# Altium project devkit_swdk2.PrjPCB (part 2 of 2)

## Sheet Application Interfaces.SchDoc: APPLICATION INTERFACES
size B; DocumentNumber: 5; SheetNumber: 5; SheetTotal: 6
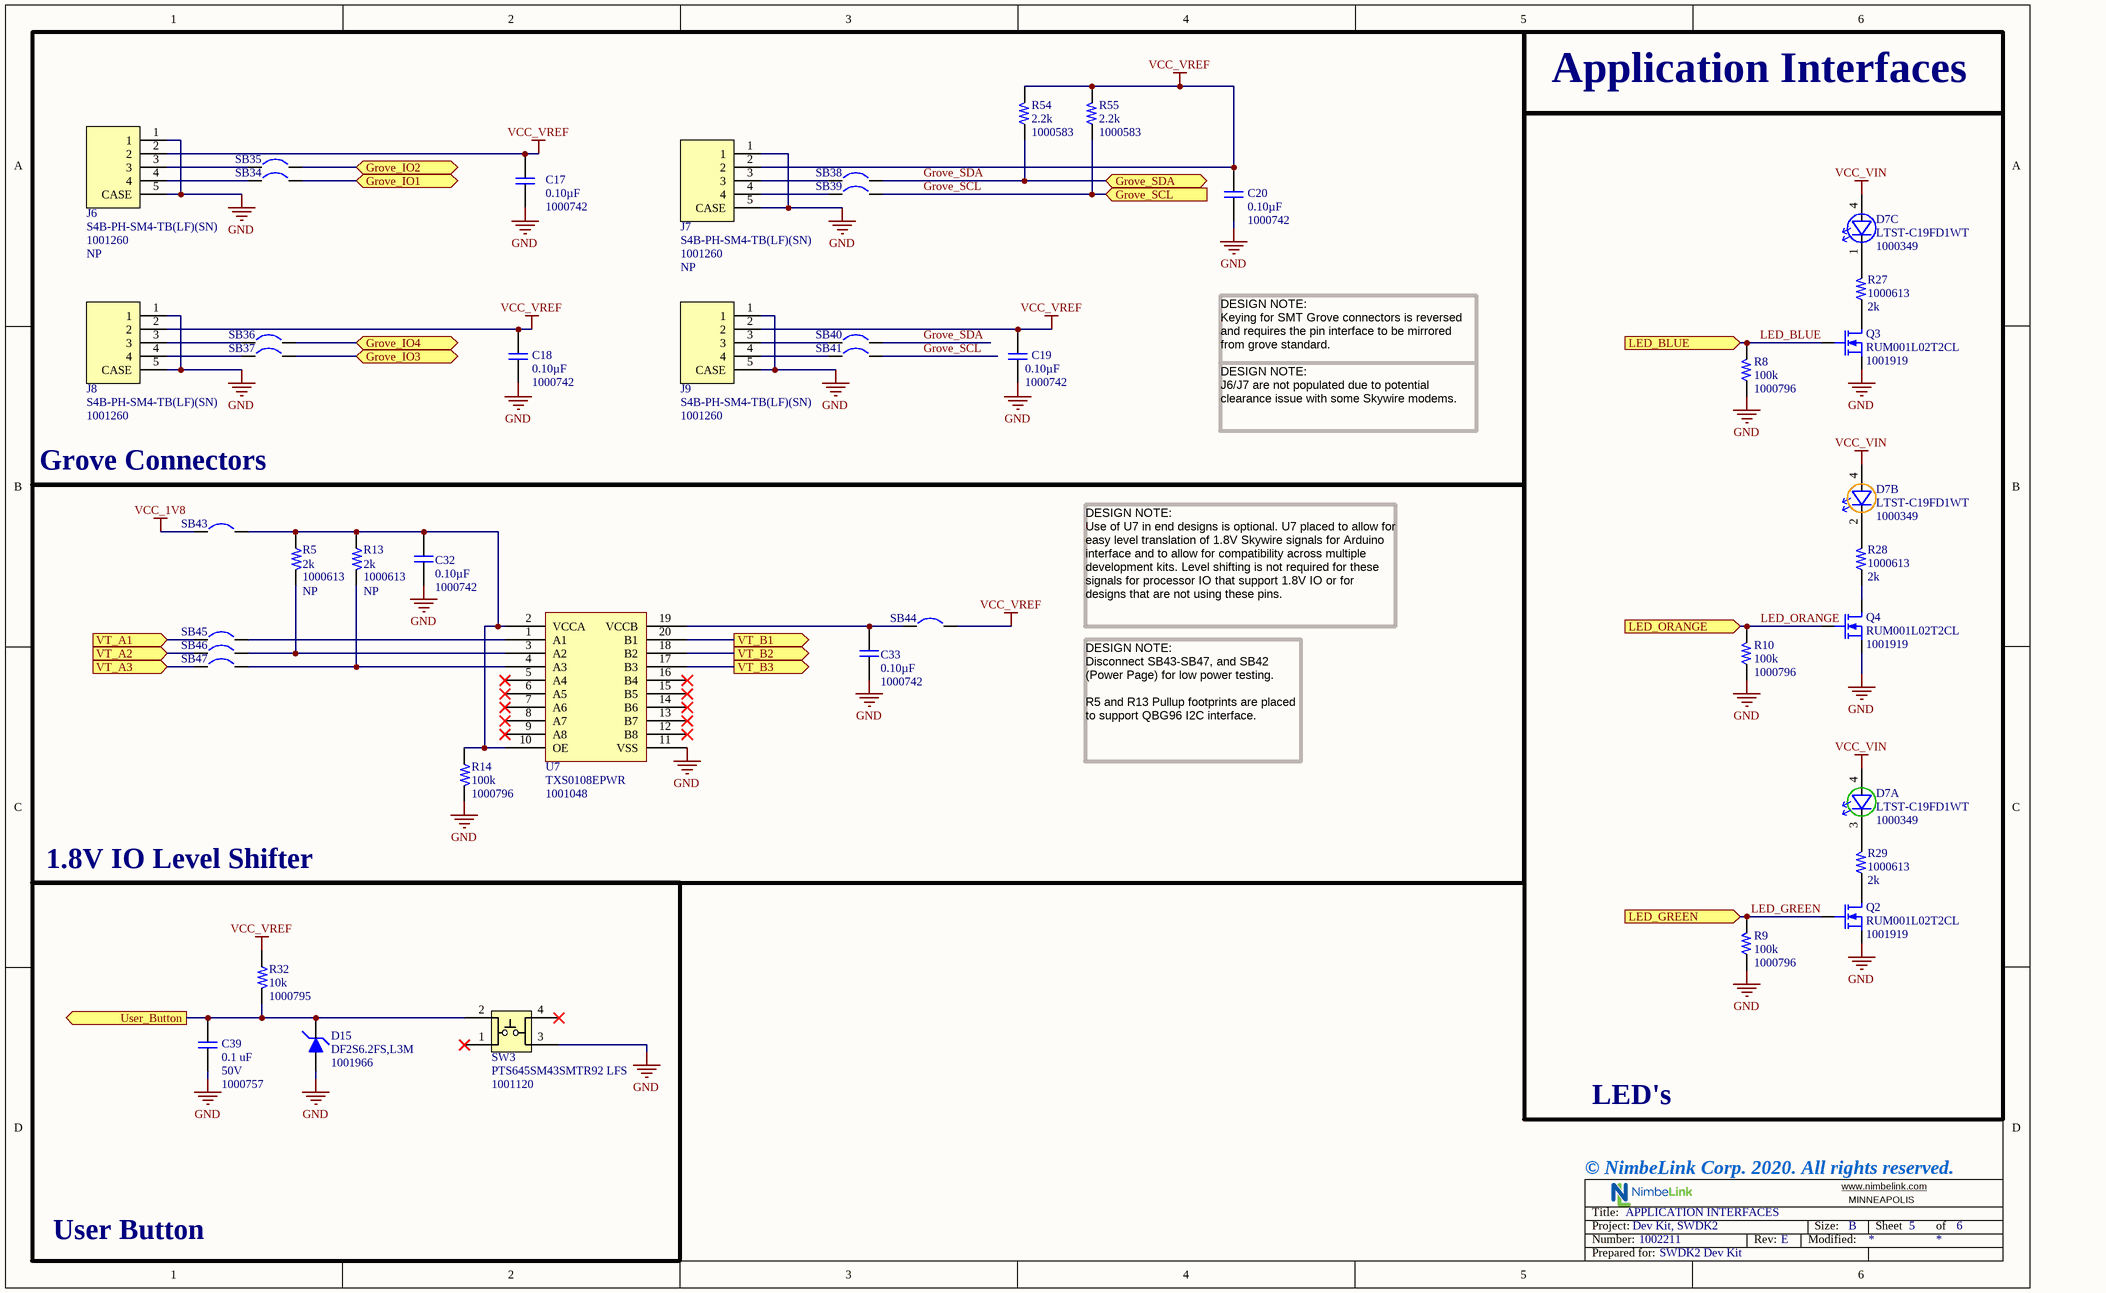
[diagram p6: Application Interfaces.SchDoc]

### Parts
C17  Capacitance: 0.10µF  Part_Number: 1000742  [0402]
C18  Capacitance: 0.10µF  Part_Number: 1000742  [0402]
C19  Capacitance: 0.10µF  Part_Number: 1000742  [0402]
C20  Capacitance: 0.10µF  Part_Number: 1000742  [0402]
C32  Capacitance: 0.10µF  Part_Number: 1000742  [0402]
C33  Capacitance: 0.10µF  Part_Number: 1000742  [0402]
C39  Part_Number: 1000757  Capacitance: 0.1 uF  Voltage_Rating: 50V  [0603]  (hidden comment: CAPACITOR)
D7  Part_Number: 1000349  [LTST-C19FD1WT]  (hidden comment: lTST-C19FD1WT)  (parts A,B,C of 3)
D15  Manufacturer_Part_Number1: DF2S6.2FS,L3M  Part_Number: 1001966  [SOD-923]  (hidden comment: TVS)
J6  Population: NP  Part_Number: 1001260  [S4B-PH-SM4-TB(LF)(SN)]  (hidden comment: S4B-PH-SM4-TB(LF)(SN))
J7  Population: NP  Part_Number: 1001260  [S4B-PH-SM4-TB(LF)(SN)]  (hidden comment: S4B-PH-SM4-TB(LF)(SN))
J8  Part_Number: 1001260  [S4B-PH-SM4-TB(LF)(SN)]  (hidden comment: S4B-PH-SM4-TB(LF)(SN))
J9  Part_Number: 1001260  [S4B-PH-SM4-TB(LF)(SN)]  (hidden comment: S4B-PH-SM4-TB(LF)(SN))
Q2  Manufacturer_Part_Number1: RUM001L02T2CL  Part_Number: 1001919  [SOT-723]  (hidden comment: MOSFET_N)
Q3  Manufacturer_Part_Number1: RUM001L02T2CL  Part_Number: 1001919  [SOT-723]  (hidden comment: MOSFET_N)
Q4  Manufacturer_Part_Number1: RUM001L02T2CL  Part_Number: 1001919  [SOT-723]  (hidden comment: MOSFET_N)
R5  Population: NP  Part_Number: 1000613  [0603]  (hidden comment: 2K)
R8  Part_Number: 1000796  Resistance_Ohms: 100k  [0402]  (hidden comment: R, 100K, 1%, 1/16W,  0402)
R9  Part_Number: 1000796  Resistance_Ohms: 100k  [0402]  (hidden comment: R, 100K, 1%, 1/16W,  0402)
R10  Part_Number: 1000796  Resistance_Ohms: 100k  [0402]  (hidden comment: R, 100K, 1%, 1/16W,  0402)
R13  Population: NP  Part_Number: 1000613  [0603]  (hidden comment: 2K)
R14  Part_Number: 1000796  Resistance_Ohms: 100k  [0402]  (hidden comment: R, 100K, 1%, 1/16W,  0402)
R27  Part_Number: 1000613  [0603]  (hidden comment: 2K)
R28  Part_Number: 1000613  [0603]  (hidden comment: 2K)
R29  Part_Number: 1000613  [0603]  (hidden comment: 2K)
R32  Part_Number: 1000795  Resistance_Ohms: 10k  [0402]  (hidden comment: R, 10K, 1%, 1/16W,  0402)
R54  Part_Number: 1000583  Resistance_Ohms: 2.2k  [0402]  (hidden comment: R, 2.2K, 1%, 1/10W, 0402)
R55  Part_Number: 1000583  Resistance_Ohms: 2.2k  [0402]  (hidden comment: R, 2.2K, 1%, 1/10W, 0402)
SB34  Solder Bridge  [Solder Bridge 0603 Closed]  (value not drawn)
SB35  Solder Bridge  [Solder Bridge 0603 Closed]  (value not drawn)
SB36  Solder Bridge  [Solder Bridge 0603 Closed]  (value not drawn)
SB37  Solder Bridge  [Solder Bridge 0603 Closed]  (value not drawn)
SB38  Solder Bridge  [Solder Bridge 0603 Closed]  (value not drawn)
SB39  Solder Bridge  [Solder Bridge 0603 Closed]  (value not drawn)
SB40  Solder Bridge  [Solder Bridge 0603 Closed]  (value not drawn)
SB41  Solder Bridge  [Solder Bridge 0603 Closed]  (value not drawn)
SB43  Solder Bridge  [Solder Bridge 0603 Closed]  (value not drawn)
SB44  Solder Bridge  [Solder Bridge 0603 Closed]  (value not drawn)
SB45  Solder Bridge  [Solder Bridge 0603 Closed]  (value not drawn)
SB46  Solder Bridge  [Solder Bridge 0603 Closed]  (value not drawn)
SB47  Solder Bridge  [Solder Bridge 0603 Closed]  (value not drawn)
SW3  Part_Number: 1001120  [PTS645SM43SMTR92 LFS]  (hidden comment: PTS645SM43SMTR92 LFS)
U7  Part_Number: 1001048  [TSSOP-20 6.5x6.4mm]  (hidden comment: TXS0108EPWR)

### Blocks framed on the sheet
Grove Connectors: C17-C20 J6-J9 R54 R55 SB34-SB41
LED's: D7 Q2-Q4 R8-R10 R27-R29

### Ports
Grove_IO1 (bidir), Grove_IO2 (bidir), Grove_IO3 (bidir), Grove_IO4 (bidir), Grove_SCL (in), Grove_SDA (bidir), LED_BLUE (in), LED_GREEN (in), LED_ORANGE (in), User_Button (out), VT_A1 (in), VT_A2 (in), VT_A3 (in), VT_B1 (out), VT_B2 (out), VT_B3 (out)

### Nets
GND: C17.2 C18.2 C19.2 C20.2 C32.2 C33.2 C39.2 D15.A J6.1 J6.5(CASE) J7.1 J7.5(CASE) J8.1 J8.5(CASE) J9.1 J9.5(CASE) Q2.2(S) Q3.2(S) Q4.2(S) R8.1 R9.1 R10.1 R14.1 SW3.3 U7.11(VSS)
VCC_1V8: SB43.1
VCC_VIN: D7.4(Anode)
VCC_VREF: C17.1 C18.1 C19.1 C20.1 J6.2 J7.2 J8.2 J9.2 R32.1 R54.2 R55.2 SB44.2
Grove_SCL: R55.1 SB39.2 SB41.2 ; port Grove_SCL
Grove_SDA: R54.1 SB38.2 SB40.2 ; port Grove_SDA
LED_BLUE: Q3.1(G) R8.2 ; port LED_BLUE
LED_GREEN: Q2.1(G) R9.2 ; port LED_GREEN
LED_ORANGE: Q4.1(G) R10.2 ; port LED_ORANGE
NetC32_1: C32.1 R5.2 R13.2 R14.2 SB43.2 U7.2(VCCA) U7.10(OE)
NetC33_1: C33.1 SB44.1 U7.19(VCCB)
NetC39_1: C39.1 D15.K R32.2 SW3.2 ; port User_Button
NetD7_1: D7.1(Cathode) R27.2
NetD7_2: D7.2(Cathode) R28.2
NetD7_3: D7.3(Cathode) R29.2
NetJ6_3: J6.3 SB35.1
NetJ6_4: J6.4 SB34.1
NetJ7_3: J7.3 SB38.1
NetJ7_4: J7.4 SB39.1
NetJ8_3: J8.3 SB36.1
NetJ8_4: J8.4 SB37.1
NetJ9_3: J9.3 SB40.1
NetJ9_4: J9.4 SB41.1
NetQ2_3: Q2.3(D) R29.1
NetQ3_3: Q3.3(D) R27.1
NetQ4_3: Q4.3(D) R28.1
NetR5_1: R5.1 SB46.2 U7.3(A2)
NetR13_1: R13.1 SB47.2 U7.4(A3)
NetSB34_2: SB34.2 ; port Grove_IO1
NetSB35_2: SB35.2 ; port Grove_IO2
NetSB36_2: SB36.2 ; port Grove_IO4
NetSB37_2: SB37.2 ; port Grove_IO3
NetSB45_1: SB45.1 ; port VT_A1
NetSB45_2: SB45.2 U7.1(A1)
NetSB46_1: SB46.1 ; port VT_A2
NetSB47_1: SB47.1 ; port VT_A3
NetU7_17: U7.17(B3) ; port VT_B3
NetU7_18: U7.18(B2) ; port VT_B2
NetU7_20: U7.20(B1) ; port VT_B1

Not connected (* = marked no-connect by the designer): SW3 1* 4*; U7 5(A4)* 6(A5)* 7(A6)* 8(A7)* 9(A8)* 12(B8)* 13(B7)* 14(B6)* 15(B5)* 16(B4)*

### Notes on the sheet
- Application Interfaces
- DESIGN NOTE:
  Keying for SMT Grove connectors is reversed and requires the pin interface to be mirrored from grove standard.
- DESIGN NOTE:
  J6/J7 are not populated due to potential clearance issue with some Skywire modems.
- DESIGN NOTE:
  Use of U7 in end designs is optional. U7 placed to allow for easy level translation of 1.8V Skywire signals for Arduino interface and to allow for compatibility across multiple development kits. Level shifting is not required for these signals for processor IO that support 1.8V IO or for designs that are not using these pins.
- DESIGN NOTE:
  Disconnect SB43-SB47, and SB42 (Power Page) for low power testing.
  R5 and R13 Pullup footprints are placed to support QBG96 I2C interface.
- 1.8V IO Level Shifter
- © NimbeLink Corp. 2020. All rights reserved.
- User Button

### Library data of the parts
C17-C20 C32 C33 = 1000742: Capacitor, 0.1 uF, 16V, 10%, X7R, 0402; Manufacturer1: Kemet; Manufacturer_Part_Number1: C0402C104K4RALTU; Item_Phase: Production; Capacitor_Type: Ceramic; Mounting_Type: Surface Mount; Operating_Temperature: -55°C ~ 125°C; Thickness_Max: 0.022" (0.55mm)
C39 = 1000757: Capacitor, 0.1 uF, 50V, 10%, X7R, 0603; Manufacturer1: TDK Corporation; Manufacturer_Part_Number1: CGA3E2X7R1H104K080AA; Item_Phase: Production; Capacitor_Type: Ceramic; Mounting_Type: Surface Mount; Operating_Temperature: -55 to 125C
D7 = 1000349: Diode, LED, BGO, 180mcd-450mcd-180mcd, 2.1x1.6mm; Manufacturer1: Lite-On Inc; Item_Phase: Production; Color: Blue, Green, Orange (BGO); Current_Test: 20mA Blue, 20mA Green, 20mA Orange; Millicandela_Rating: Blue: 180mcd, Green: 450mcd, Orange: 180mcd; Mounting_Type: Surface Mount; Operating_Temperature: -20C to 80C; Voltage_Forward_VF_Typical: 3.5V Blue, 3.5V Green, 2V Orange
D15 = 1001966: Diode, TVS, Unidirectional, 5V, SOD-923; Manufacturer1: Toshiba Semiconductor and Storage; Item_Phase: Production; Capacitance_at_Frequency: 32pF @ 1MHz; Current_Reverse_Leakage_at_Vref: 2.5uA; Mounting_Type: Surface Mount; Voltage_DC_Reverse_VR_Max: 5
J6-J9 = 1001260: Connector, Header, Male, 2.00mm, 4x1, Right Angle, SMD; Manufacturer1: JST Sales America Inc; Item_Phase: Production; Connector_Type: Header, Shrouded; Contact_Finish: Tin; Contact_Type: Male Pin; Fastening_Type: Detent Lock; Mounting_Type: Surface Mount Right Angle; Number_of_Pins: 4; Number_of_Positions_Loaded: All; Number_of_Rows: 1; Pitch: 0.079 (2.00mm)"
Q2-Q4 = 1001919: Transistor, MOSFET, N-CH, 20V, 0.100A, SOT-723; Manufacturer1: Rohm Semiconductor; Item_Phase: Production; Current_Continuous_Drain_at_25_deg_C: 100mA; Mounting_Type: Surface Mount; Operating_Temperature: -55 to 150C; Power_Max: 150 mW; Transistor_Type: NCH - FET
R5 R13 R27-R29 = 1000613: Resistor, 2K, 1%, 1/10W, 0603; Manufacturer1: Panasonic Electronic Components; Manufacturer_Part_Number1: ERJ-3EKF2001V; Item_Phase: Production; Mounting_Type: Surface Mount; Number_of_Terminations: 2; Operating_Temperature: -55°C ~ 155°C; Power: 0.1W, 1/10W; Resistor_Package: 0603 (1608 Metric); Temperature_Coefficient: ±100ppm/°C
R8-R10 R14 = 1000796: Resistor, 100K, 1%, 1/16W, 0402; Manufacturer1: Bourns Inc; Manufacturer_Part_Number1: CR0402-FX-1003GLF; Item_Phase: Production; Mounting_Type: Surface Mount; Number_of_Terminations: 2; Operating_Temperature: -55°C ~ 155°C; Power: 0.063W, 1/16W; Resistor_Package: 0402 (1005 Metric); Temperature_Coefficient: ±100ppm/°C
R32 = 1000795: Resistor, 10K, 1%, 1/16W, 0402; Manufacturer1: Bourns Inc; Manufacturer_Part_Number1: CR0402-FX-1002GLF; Item_Phase: Production; Mounting_Type: Surface Mount; Number_of_Terminations: 2; Operating_Temperature: -55°C ~ 155°C; Power: 0.063W, 1/16W; Resistor_Package: 0402 (1005 Metric); Temperature_Coefficient: ±100ppm/°C
R54 R55 = 1000583: Resistor, 2.2K, 1%, 1/10W, 0402; Manufacturer1: Panasonic Electronic Components; Manufacturer_Part_Number1: ERJ-2RKF2201X; Item_Phase: Production; Mounting_Type: Surface Mount; Number_of_Terminations: 2; Operating_Temperature: -55°C ~ 155°C; Power: 0.1W, 1/10W; Resistor_Package: 0402 (1005 Metric); Temperature_Coefficient: ±100ppm/°C
SB34-SB41 SB43-SB47 = 1002269: Resistor, Solder Bridge, 0, 1/10W, 0603; Manufacturer_Part_Number1: ERJ-3GEY0R00V; Manufacturer1: Panasonic Electronic Components; Resistance_Ohms: 0; Item_Phase: Production; Mounting_Type: Surface Mount; Operating_Temperature: -55°C ~ 155°C; Resistor_Package: 0603 (1608 Metric)
SW3 = 1001120: Switch, SPST-NO, 12V, 0.05A, 6.00x6.00mm, SMD; Manufacturer1: C&K Components; Item_Phase: Production; Actuator_Type: Button; Contact_Current_Rating_at_Voltage: 0.05A @ 12VDC; Mechanical_Life: 100,000 Cycles; Mounting_Type: Surface Mount; Operating_Force: 160gf; Operating_Temperature: -20°C ~ 60°C
U7 = 1001048: IC, Level Shifter, Bidirectional, OD/Push/Pull , TSSOP-20; Manufacturer1: Texas Instruments; Item_Phase: Production; Mounting_Type: Surface Mount; Operating_Temperature: -40°C ~ 85°C; Output_Type: Voltage

## Sheet ECO LIST.SchDoc: ECO LIST
size C; DocumentNumber: 6; SheetNumber: 6; SheetTotal: 6
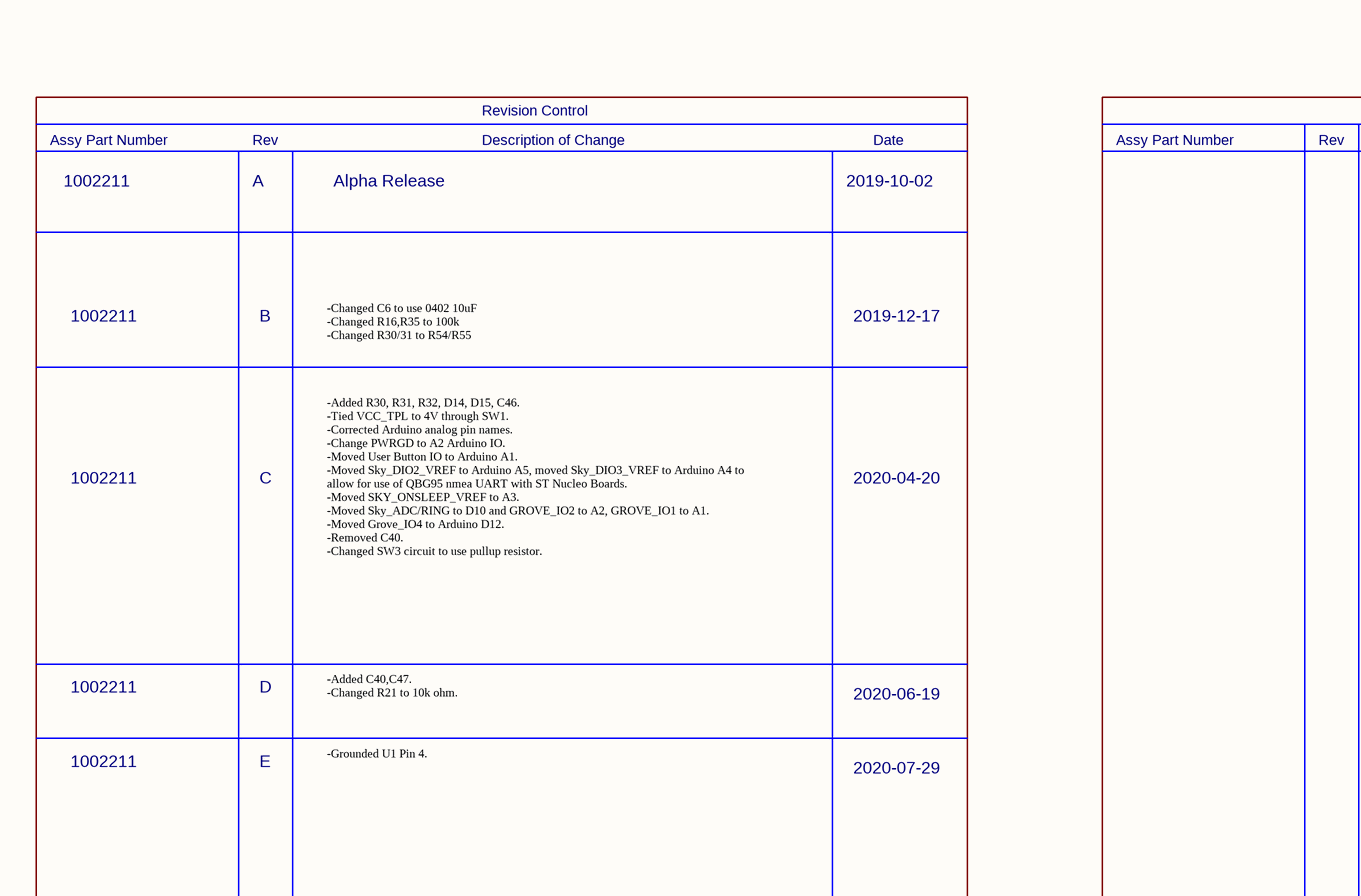
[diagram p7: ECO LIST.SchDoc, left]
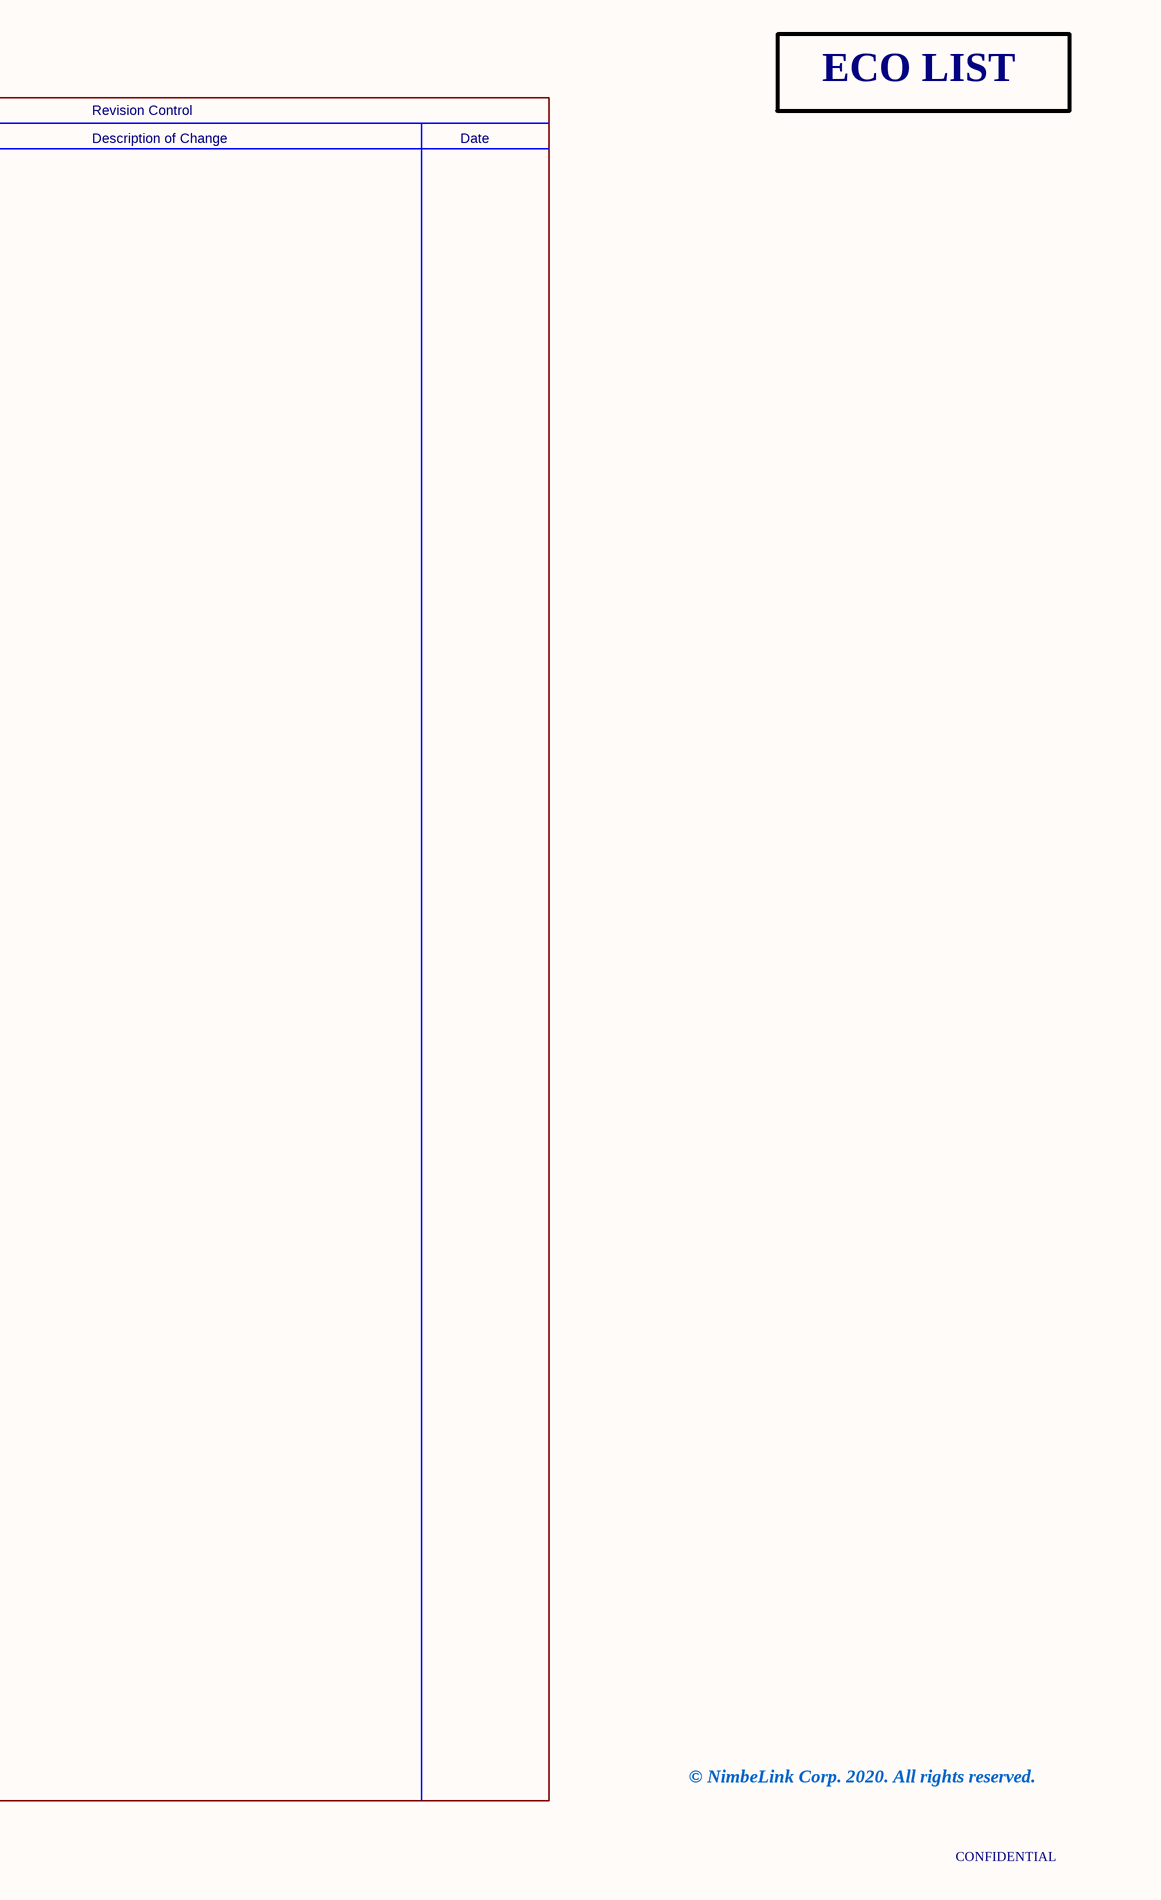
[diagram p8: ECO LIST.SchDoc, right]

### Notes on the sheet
- Assy Part Number
- Rev
- Description of Change
- Revision Control
- Date
- ECO LIST
- 1002211
- A
- Alpha Release
- 2019-10-02
- B
- -Changed C6 to use 0402 10uF
  -Changed R16,R35 to 100k
  -Changed R30/31 to R54/R55
- 2019-12-17
- C
- 2020-04-20
- -Added R30, R31, R32, D14, D15, C46.
  -Tied VCC_TPL to 4V through SW1.
  -Corrected Arduino analog pin names.
  -Change PWRGD to A2 Arduino IO.
  -Moved User Button IO to Arduino A1.
  -Moved Sky_DIO2_VREF to Arduino A5, moved Sky_DIO3_VREF to Arduino A4 to allow for use of QBG95 nmea UART with ST Nucleo Boards.
  -Moved SKY_ONSLEEP_VREF to A3.
  -Moved Sky_ADC/RING to D10 and GROVE_IO2 to A2, GROVE_IO1 to A1.
  -Moved Grove_IO4 to Arduino D12.
  -Removed C40.
  -Changed SW3 circuit to use pullup resistor.
- D
- -Added C40,C47.
  -Changed R21 to 10k ohm.
- 2020-06-19
- E
- -Grounded U1 Pin 4.
- 2020-07-29
- © NimbeLink Corp. 2020. All rights reserved.
- CONFIDENTIAL

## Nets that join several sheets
GND: TOP (31 pins), Power (30 pins), Skywire (42 pins), Application Interfaces (25 pins)
VCC_1V8: Power (5 pins), Application Interfaces (SB43.1)
VCC_3V3_FTDI: TOP (C16.1 SB1.1 U4.3), Power (D11.2 SB32.1)
VCC_4V0: TOP (C43.1 SW1.4), Power (8 pins), Skywire (C22.1 D1.1 J2.1 R4.1)
VCC_ARD_3V3: TOP (SB3.1), Power (SB42.1)
VCC_ARD_IOREF: TOP (SB2.1), Power (D11.1 SB33.1)
VCC_SKY_VREF: Power (Q8.3 SB52.2), Skywire (J1.1 R3.2)
VCC_SKY_VUSB: TOP (D6.2), Skywire (6 pins)
VCC_TPL: TOP (C46.1 SW1.3), Skywire (C4.1 U1.1)
VCC_VIN: TOP (SB5.1), Power (6 pins), Application Interfaces (D7.4)
VCC_VREF: Power (9 pins), Application Interfaces (12 pins)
